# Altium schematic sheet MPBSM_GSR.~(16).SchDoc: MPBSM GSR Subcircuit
size 431 x 279 mm; Date: Not shown in title block; ApprovedBy: Not shown in title block; CheckedBy: Not shown in title block; Author: Not shown in title block; CompanyName: Not shown in title block; Engineer: Not shown in title block; Organization: Not shown in title block; Address1: Not shown in title block; Address2: Not shown in title block; Address3: Not shown in title block; Address4: Not shown in title block; DocumentNumber: 9; Revision: Use project parameter SCH_Rev; SheetNumber: 8; SheetTotal: 12; PageSetup: Record=PageOptions¦CenterHorizontal=True¦CenterVertical=True¦PrintScale=1.00¦XCorrection=1.00¦YCorrection=1.00¦PrintKind=0¦BorderSize=5000000¦LeftOffset=0¦BottomOffset=0¦Orientation=2¦PaperLength=1000¦PaperWidth=1000¦Scale=100¦PaperSource=15¦PrintQuality=600¦MediaType=1¦DitherType=10¦PaperKind=Letter¦PrintScaleMode=1
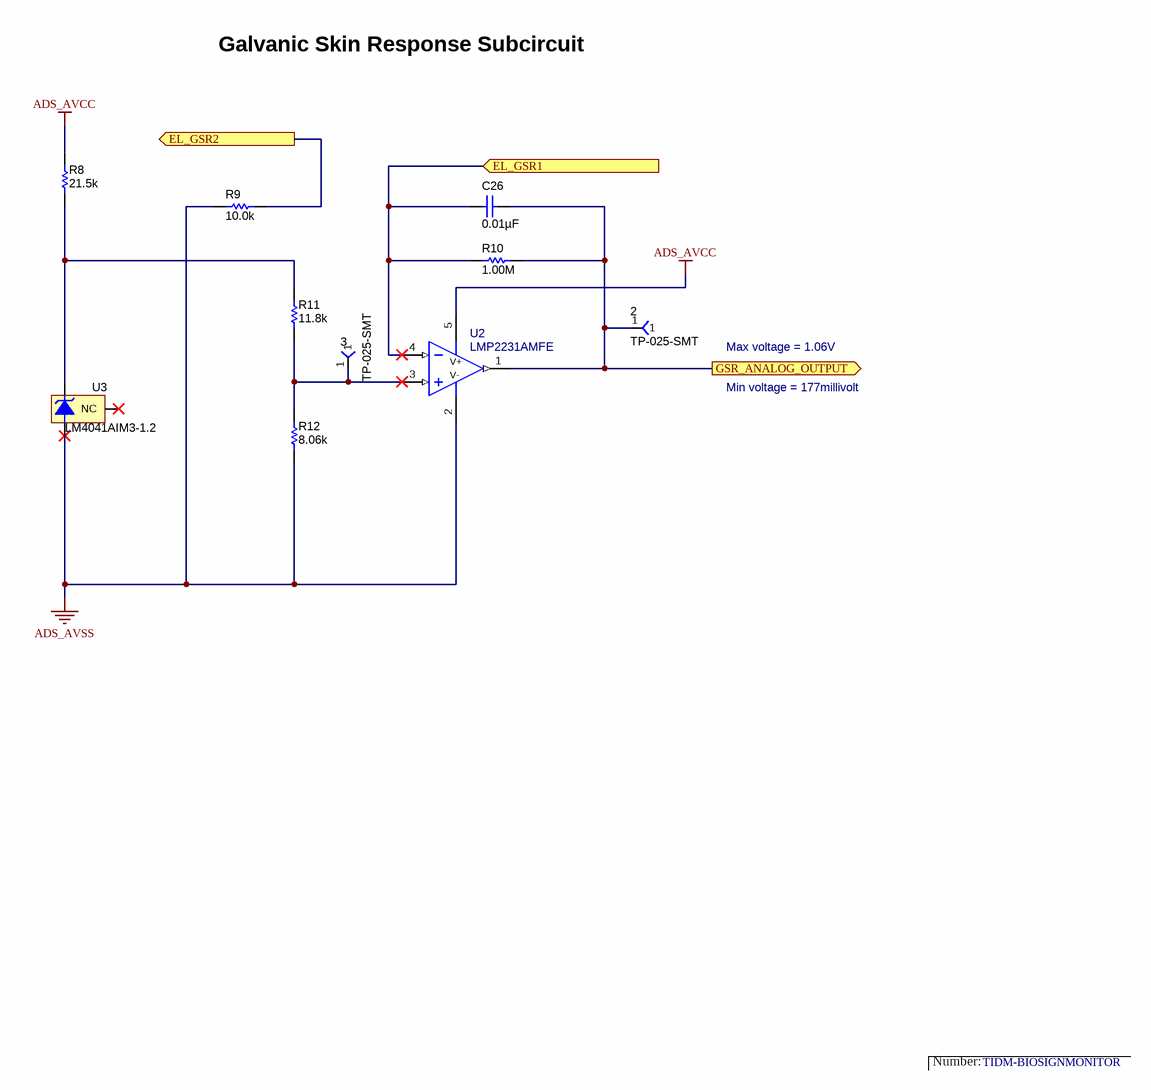
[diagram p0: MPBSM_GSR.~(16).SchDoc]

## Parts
2  TP-025-SMT  [TP_25MIL-SMT]
3  TP-025-SMT  [TP_25MIL-SMT]
C26  ValueDisplayed: 0.01µF  [0402]  (hidden comment: C1005X7R1E103K)
R8  ValueDisplayed: 21.5k  [0402]  (hidden comment: CRCW040221K5FKED)
R9  ValueDisplayed: 10.0k  [0402]  (hidden comment: CRCW040210K0FKED)
R10  ValueDisplayed: 1.00M  [0402]  (hidden comment: ERJ-2RKF1004X)
R11  ValueDisplayed: 11.8k  [0402]  (hidden comment: CRCW040211K8FKED)
R12  ValueDisplayed: 8.06k  [0402]  (hidden comment: CRCW04028K06FKED)
U2  LMP2231AMFE  [MF05A_L]
U3  LM4041AIM3-1.2  [MF03A_N]

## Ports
EL_GSR1 (in), EL_GSR2 (out), GSR_ANALOG_OUTPUT (out)

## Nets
ADS_AVCC: R8.2 U2.5(V+)
ADS_AVSS: R9.1 R12.1 U2.2(V-) U3.2(-V)
EL_GSR1: C26.2 R10.1 U2.4(IN-) ; port EL_GSR1
EL_GSR2: R9.2 ; port EL_GSR2
GSR_ANALOG_OUTPUT: 2.1 C26.1 R10.2 U2.1(OUT) ; port GSR_ANALOG_OUTPUT
Net3_1: 3.1 R11.1 R12.2 U2.3(IN+)
NetR8_1: R8.1 R11.2 U3.1(+V)

Not connected (* = marked no-connect by the designer): U3 3(NC)*

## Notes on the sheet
- Galvanic Skin Response Subcircuit
- Max voltage = 1.06V
- Min voltage = 177millivolt
- Number:
- TIDM-BIOSIGNMONITOR

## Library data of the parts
2 3 = TP-025-SMT: Test Point, O.025"; Manufacturer: STD; Value: STD
C26 = C1005X7R1E103K: CAP, CERM, 0.01 µF, 25 V, +/- 10%, X7R, 0402; Manufacturer: TDK; Polarized: N; CompType: Capacitor; Value: 0.01uF; U/M: EA; Cap_F: 0.00000001; Tolerance_%: 10; ESR_ohm: 0.0623; Value1: 0.0623 ohm; VDC_V: 25; Value2: 25V; TaMin_C: -55; TaMax_C: 125
R8 = CRCW040221K5FKED: RES, 21.5 k, 1%, 0.063 W, 0402; Manufacturer: Vishay-Dale; CompType: Resistor; Value: 21.5k; Res_ohm: 21500; Value_Code: 21k5; Tolerance_%: 1; Power_W: 0.063; Value2: 0.063W; VDC_V: 50; TempCo: 100 ppm/C; EIA_Code: E96; U/M: EA
R9 = CRCW040210K0FKED: RES, 10.0 k, 1%, 0.063 W, 0402; Manufacturer: Vishay-Dale; CompType: Resistor; Value: 10.0k; Res_ohm: 10000; Value_Code: 10k0; Tolerance_%: 1; Power_W: 0.063; Value2: 0.063W; VDC_V: 50; TempCo: 100 ppm/C; EIA_Code: E96; U/M: EA
R10 = ERJ-2RKF1004X: RES, 1.00 M, 1%, 0.1 W, 0402; Manufacturer: Panasonic; CompType: Resistor; Value: 1.00Meg; Res_ohm: 1000000; Value_Code: 1M00; Tolerance_%: 1; Power_W: 0.1; Value2: 0.1W; VDC_V: 50; TempCo: 100 ppm/C; EIA_Code: E96; U/M: EA
R11 = CRCW040211K8FKED: RES, 11.8 k, 1%, 0.063 W, 0402; Manufacturer: Vishay-Dale; CompType: Resistor; Value: 11.8k; Res_ohm: 11800; Value_Code: 11k8; Tolerance_%: 1; Power_W: 0.063; Value2: 0.063W; VDC_V: 50; TempCo: 100 ppm/C; EIA_Code: E96; U/M: EA
R12 = CRCW04028K06FKED: RES, 8.06 k, 1%, 0.063 W, 0402; Manufacturer: Vishay-Dale; CompType: Resistor; Value: 8.06k; Res_ohm: 8060; Value_Code: 8k06; Tolerance_%: 1; Power_W: 0.063; Value2: 0.063W; VDC_V: 50; TempCo: 100 ppm/C; EIA_Code: E96; U/M: EA
U2 = LMP2231AMFE: Single Micropower Precision Op Amp; Manufacturer: National Semiconductor; Characteristics: LMP2231AMFE Single Micropower Precision Op Amp; CompType: IC; Value: Analog; TaMin_C: -40 °C; TaMax_C: 125 °C; PowerWise: N; InputBiasCurrent: 0.02 pA; InputOffsetVoltage: 10 µV; SupplyCurrent: 10 µA; VoltageSupplyMax_V: 5.5 V; VoltageSupplyMin_V: 1.6 V; OutputType: Rail-to-Rail; SlewRate: 0.058 V/µs; GainBandwidthProduct: 130 kHz; Value1: 1.6 V - 5.5 V
U3 = LM4041AIM3-1.2: Precision Micropower Shunt Voltage Reference, 3-pin SOT-23; Manufacturer: Texas Instruments; PackageTopMarking: R1A*XTT; PowerWise: N; CompType: IC; SupplyVoltageMax_V: Not Applicable; SupplyCurrent: 12 mA; SymbolCreator: a0272897; TaMax_C: 85°C; TaMin_C: -40°C; Value: Analog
